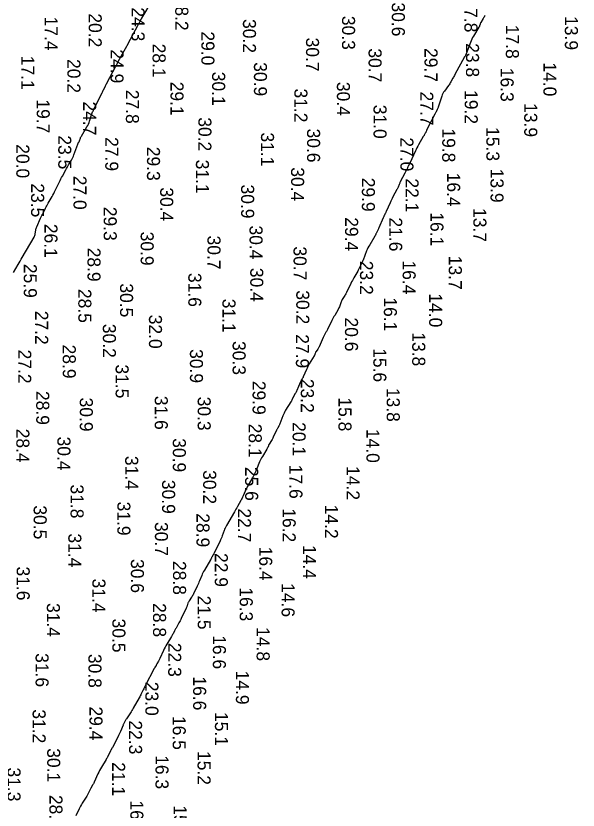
# Model space of a CAD drawing. Extents: x 1178573 to 1187098, y 693282 to 751751.
# Drawn here: x 1180061 to 1180599, y 711569 to 712330 of the extents above; entities that cross this region are included whole.
import ezdxf

# ---------------------------------------------------------------- set-up
doc = ezdxf.new("R2010")
doc.units = 0
doc.layers.add('V-HYDS-MAJR', color=7, linetype='Continuous')
doc.layers.add('V-HYDS-SOUN', color=7, linetype='Continuous')

msp = doc.modelspace()

# ---------------------------------------------------------------- linework, layer by layer
at = {"layer": 'V-HYDS-MAJR'}
for points in [[(1180058.4, 712084.02), (1180062.67, 712091.72), (1180063.61, 712093.4), (1180064.56, 712095.08), (1180065.52, 712096.75), (1180066.49, 712098.42), (1180078.04, 712118.1), (1180078.44, 712118.85), (1180078.75, 712119.63), (1180078.99, 712120.43), (1180079.14, 712121.27), (1180079.62, 712124.66), (1180079.77, 712125.5), (1180079.97, 712126.32), (1180080.23, 712127.12), (1180080.55, 712127.91), (1180084.2, 712136.14), (1180084.76, 712137.37), (1180085.33, 712138.59), (1180085.93, 712139.79), (1180086.55, 712140.99), (1180089.07, 712145.76), (1180089.7, 712146.95), (1180090.34, 712148.14), (1180090.99, 712149.32), (1180091.64, 712150.5), (1180095.2, 712156.86), (1180096.01, 712158.32), (1180096.79, 712159.79), (1180097.54, 712161.27), (1180098.27, 712162.77), (1180102.22, 712170.97), (1180102.92, 712172.39), (1180103.63, 712173.8), (1180104.36, 712175.2), (1180105.11, 712176.59), (1180108.36, 712182.51), (1180109.01, 712183.7), (1180109.68, 712184.89), (1180110.36, 712186.06), (1180111.05, 712187.23), (1180113.82, 712191.9), (1180114.49, 712193.09), (1180115.09, 712194.3), (1180115.64, 712195.53), (1180116.13, 712196.8), (1180119.84, 712207.19), (1180119.95, 712207.48), (1180120.08, 712207.75), (1180120.22, 712208.01), (1180120.38, 712208.27), (1180121.04, 712209.29), (1180121.19, 712209.55), (1180121.33, 712209.81), (1180121.46, 712210.09), (1180121.56, 712210.37), (1180122.42, 712212.89), (1180122.61, 712213.4), (1180122.83, 712213.9), (1180123.07, 712214.38), (1180123.34, 712214.85), (1180128.62, 712223.63), (1180129.38, 712224.97), (1180130.05, 712226.34), (1180130.65, 712227.74), (1180131.17, 712229.19), (1180133.46, 712236.16), (1180133.77, 712237.05), (1180134.11, 712237.93), (1180134.48, 712238.8), (1180134.87, 712239.65), (1180136.51, 712243.04), (1180136.92, 712243.89), (1180137.33, 712244.74), (1180137.75, 712245.58), (1180138.17, 712246.43), (1180143.06, 712256.23), (1180143.48, 712257.06), (1180143.89, 712257.89), (1180144.3, 712258.71), (1180144.72, 712259.54), (1180146.37, 712262.84), (1180146.79, 712263.67), (1180147.21, 712264.49), (1180147.64, 712265.31), (1180148.07, 712266.12), (1180156.09, 712281.13), (1180156.29, 712281.51), (1180156.48, 712281.89), (1180156.67, 712282.28), (1180156.86, 712282.66), (1180157.58, 712284.22), (1180157.77, 712284.6), (1180157.96, 712284.99), (1180158.16, 712285.37), (1180158.36, 712285.74), (1180167.17, 712301.63), (1180167.25, 712301.79), (1180167.34, 712301.94), (1180167.43, 712302.09), (1180167.52, 712302.24), (1180167.89, 712302.84), (1180167.98, 712302.99), (1180168.07, 712303.15), (1180168.16, 712303.3), (1180168.24, 712303.46), (1180177.45, 712320.96), (1180177.74, 712321.51), (1180178.03, 712322.06), (1180178.32, 712322.61), (1180178.61, 712323.16), (1180180.31, 712326.38), (1180180.32, 712326.41), (1180180.34, 712326.45), (1180180.35, 712326.48), (1180180.37, 712326.51), (1180180.43, 712326.64), (1180180.44, 712326.67), (1180180.46, 712326.7), (1180180.48, 712326.73), (1180180.49, 712326.76), (1180180.93, 712327.4), (1180181, 712327.52), (1180181.08, 712327.64), (1180181.15, 712327.76), (1180181.23, 712327.88), (1180191.16, 712344.58)], [(1180509.77, 712330.41), (1180509.42, 712329.63), (1180509.04, 712328.87), (1180508.64, 712328.11), (1180508.22, 712327.37), (1180506.02, 712323.66), (1180505.82, 712323.3), (1180505.64, 712322.93), (1180505.49, 712322.55), (1180505.35, 712322.15), (1180504.87, 712320.56), (1180504.74, 712320.17), (1180504.58, 712319.79), (1180504.4, 712319.42), (1180504.19, 712319.06), (1180499.06, 712310.73), (1180498.17, 712309.2), (1180497.36, 712307.64), (1180496.63, 712306.04), (1180495.97, 712304.4), (1180491.95, 712293.56), (1180491.9, 712293.44), (1180491.85, 712293.31), (1180491.8, 712293.19), (1180491.74, 712293.08), (1180491.51, 712292.61), (1180491.45, 712292.49), (1180491.39, 712292.37), (1180491.33, 712292.26), (1180491.27, 712292.14), (1180490.87, 712291.33), (1180490.78, 712291.16), (1180490.7, 712290.99), (1180490.61, 712290.82), (1180490.51, 712290.65), (1180481.22, 712273.84), (1180480.72, 712272.94), (1180480.22, 712272.04), (1180479.73, 712271.15), (1180479.23, 712270.25), (1180477.24, 712266.67), (1180476.73, 712265.79), (1180476.19, 712264.92), (1180475.63, 712264.07), (1180475.03, 712263.23), (1180471.19, 712257.99), (1180470.39, 712256.81), (1180469.7, 712255.58), (1180469.11, 712254.31), (1180468.61, 712252.98), (1180465.26, 712242.7), (1180465.05, 712242.11), (1180464.82, 712241.52), (1180464.56, 712240.94), (1180464.28, 712240.37), (1180463.11, 712238.12), (1180462.81, 712237.56), (1180462.52, 712237), (1180462.23, 712236.43), (1180461.94, 712235.87), (1180454.39, 712221.12), (1180454.24, 712220.83), (1180454.1, 712220.53), (1180453.97, 712220.23), (1180453.84, 712219.93), (1180453.34, 712218.72), (1180453.22, 712218.42), (1180453.08, 712218.13), (1180452.93, 712217.84), (1180452.77, 712217.55), (1180451.78, 712215.85), (1180451.56, 712215.47), (1180451.34, 712215.09), (1180451.12, 712214.71), (1180450.9, 712214.33), (1180446.37, 712206.47), (1180445.56, 712205.03), (1180444.78, 712203.57), (1180444.03, 712202.09), (1180443.32, 712200.59), (1180437.88, 712188.85), (1180437.7, 712188.46), (1180437.52, 712188.08), (1180437.33, 712187.7), (1180437.14, 712187.31), (1180436.38, 712185.79), (1180436.19, 712185.41), (1180436, 712185.03), (1180435.82, 712184.64), (1180435.64, 712184.26), (1180434.43, 712181.64), (1180434.16, 712181.08), (1180433.89, 712180.52), (1180433.61, 712179.96), (1180433.32, 712179.41), (1180428.87, 712170.94), (1180428.56, 712170.33), (1180428.27, 712169.72), (1180427.98, 712169.1), (1180427.71, 712168.48), (1180426.65, 712165.97), (1180426.38, 712165.35), (1180426.09, 712164.73), (1180425.8, 712164.12), (1180425.49, 712163.52), (1180421.85, 712156.55), (1180421.15, 712155.19), (1180420.46, 712153.81), (1180419.8, 712152.43), (1180419.16, 712151.03), (1180415.32, 712142.56), (1180415.09, 712142.05), (1180414.86, 712141.55), (1180414.62, 712141.04), (1180414.38, 712140.54), (1180413.41, 712138.52), (1180413.17, 712138.02), (1180412.94, 712137.51), (1180412.71, 712137), (1180412.49, 712136.49), (1180408.38, 712127.01), (1180408.12, 712126.42), (1180407.85, 712125.83), (1180407.57, 712125.25), (1180407.29, 712124.67), (1180405.77, 712121.66), (1180405.66, 712121.43), (1180405.55, 712121.2), (1180405.44, 712120.96), (1180405.34, 712120.73), (1180404.94, 712119.78), (1180404.83, 712119.55), (1180404.72, 712119.32), (1180404.6, 712119.09), (1180404.47, 712118.87), (1180399.5, 712110.73), (1180398.66, 712109.28), (1180397.88, 712107.8), (1180397.18, 712106.29), (1180396.54, 712104.75), (1180393.15, 712096.05), (1180393.02, 712095.72), (1180392.89, 712095.39), (1180392.74, 712095.06), (1180392.6, 712094.74), (1180392, 712093.44), (1180391.85, 712093.11), (1180391.7, 712092.79), (1180391.55, 712092.47), (1180391.39, 712092.15), (1180389.57, 712088.4), (1180389.2, 712087.67), (1180388.83, 712086.94), (1180388.45, 712086.22), (1180388.05, 712085.51), (1180384.39, 712079.03), (1180383.65, 712077.7), (1180382.94, 712076.37), (1180382.25, 712075.03), (1180381.57, 712073.67), (1180377.4, 712065.12), (1180377, 712064.33), (1180376.57, 712063.56), (1180376.12, 712062.79), (1180375.64, 712062.05), (1180373.68, 712059.09), (1180373.21, 712058.33), (1180372.79, 712057.56), (1180372.42, 712056.76), (1180372.1, 712055.93), (1180370.78, 712052.2), (1180370.44, 712051.31), (1180370.06, 712050.43), (1180369.64, 712049.57), (1180369.19, 712048.73), (1180365.98, 712043.07), (1180365.3, 712041.84), (1180364.63, 712040.61), (1180363.97, 712039.36), (1180363.33, 712038.12), (1180358.98, 712029.49), (1180358.66, 712028.85), (1180358.33, 712028.22), (1180358, 712027.59), (1180357.66, 712026.96), (1180356.3, 712024.44), (1180355.97, 712023.81), (1180355.65, 712023.18), (1180355.34, 712022.53), (1180355.04, 712021.89), (1180350.98, 712012.9), (1180350.72, 712012.36), (1180350.43, 712011.83), (1180350.12, 712011.32), (1180349.79, 712010.82), (1180348.13, 712008.47), (1180347.92, 712008.16), (1180347.75, 712007.84), (1180347.59, 712007.5), (1180347.47, 712007.15), (1180347.02, 712005.73), (1180346.89, 712005.38), (1180346.75, 712005.03), (1180346.59, 712004.7), (1180346.41, 712004.38), (1180341.67, 711996.49), (1180340.94, 711995.22), (1180340.25, 711993.93), (1180339.6, 711992.61), (1180338.99, 711991.27), (1180335.88, 711984.1), (1180335.67, 711983.65), (1180335.45, 711983.2), (1180335.22, 711982.75), (1180334.97, 711982.32), (1180333.95, 711980.59), (1180333.7, 711980.15), (1180333.46, 711979.71), (1180333.24, 711979.26), (1180333.04, 711978.8), (1180329.72, 711971.08), (1180329.39, 711970.35), (1180329.04, 711969.62), (1180328.67, 711968.91), (1180328.27, 711968.21), (1180326.26, 711964.77), (1180326.06, 711964.4), (1180325.86, 711964.02), (1180325.68, 711963.64), (1180325.5, 711963.25), (1180324.85, 711961.67), (1180324.67, 711961.28), (1180324.48, 711960.9), (1180324.28, 711960.52), (1180324.06, 711960.16), (1180318.97, 711952.16), (1180318.19, 711950.84), (1180317.47, 711949.49), (1180316.83, 711948.1), (1180316.25, 711946.68), (1180313.42, 711939.09), (1180313.22, 711938.57), (1180312.99, 711938.06), (1180312.75, 711937.56), (1180312.49, 711937.07), (1180311.41, 711935.12), (1180311.14, 711934.63), (1180310.88, 711934.14), (1180310.63, 711933.64), (1180310.39, 711933.13), (1180307.17, 711926.24), (1180306.8, 711925.48), (1180306.4, 711924.73), (1180305.98, 711923.99), (1180305.53, 711923.27), (1180303.26, 711919.7), (1180303.04, 711919.33), (1180302.83, 711918.94), (1180302.64, 711918.55), (1180302.46, 711918.15), (1180301.8, 711916.53), (1180301.62, 711916.12), (1180301.43, 711915.73), (1180301.23, 711915.34), (1180301.01, 711914.97), (1180296.74, 711907.97), (1180295.98, 711906.66), (1180295.28, 711905.33), (1180294.63, 711903.97), (1180294.05, 711902.58), (1180291.16, 711895.29), (1180290.88, 711894.6), (1180290.57, 711893.92), (1180290.25, 711893.25), (1180289.91, 711892.59), (1180288.52, 711889.95), (1180288.17, 711889.29), (1180287.82, 711888.64), (1180287.46, 711887.98), (1180287.09, 711887.33), (1180282.24, 711878.77), (1180281.67, 711877.72), (1180281.12, 711876.66), (1180280.61, 711875.58), (1180280.13, 711874.49), (1180278.26, 711870.08), (1180277.78, 711868.99), (1180277.27, 711867.91), (1180276.73, 711866.85), (1180276.15, 711865.8), (1180272.89, 711860.03), (1180272.15, 711858.72), (1180271.4, 711857.41), (1180270.66, 711856.11), (1180269.91, 711854.8), (1180262.31, 711841.62), (1180261.67, 711840.45), (1180261.08, 711839.25), (1180260.54, 711838.04), (1180260.05, 711836.8), (1180258.2, 711831.78), (1180257.72, 711830.54), (1180257.22, 711829.3), (1180256.69, 711828.08), (1180256.13, 711826.87), (1180250.53, 711815.15), (1180250.32, 711814.72), (1180250.1, 711814.3), (1180249.86, 711813.88), (1180249.61, 711813.48), (1180248.33, 711811.46), (1180248.21, 711811.25), (1180248.09, 711811.04), (1180247.99, 711810.82), (1180247.89, 711810.59), (1180247.54, 711809.68), (1180247.44, 711809.45), (1180247.34, 711809.23), (1180247.23, 711809.02), (1180247.11, 711808.8), (1180241.14, 711798.82), (1180240.44, 711797.61), (1180239.79, 711796.37), (1180239.18, 711795.11), (1180238.63, 711793.83), (1180236.48, 711788.65), (1180235.94, 711787.36), (1180235.38, 711786.07), (1180234.8, 711784.8), (1180234.21, 711783.53), (1180230.67, 711776.09), (1180230.26, 711775.28), (1180229.83, 711774.49), (1180229.37, 711773.71), (1180228.87, 711772.95), (1180226.52, 711769.46), (1180226.19, 711768.93), (1180225.9, 711768.39), (1180225.65, 711767.82), (1180225.44, 711767.24), (1180224.67, 711764.86), (1180224.46, 711764.27), (1180224.24, 711763.69), (1180224, 711763.12), (1180223.74, 711762.55), (1180219.03, 711752.69), (1180218.5, 711751.59), (1180217.95, 711750.51), (1180217.38, 711749.43), (1180216.79, 711748.36), (1180213.96, 711743.32), (1180213.59, 711742.65), (1180213.22, 711741.97), (1180212.87, 711741.3), (1180212.51, 711740.62), (1180211.11, 711737.88), (1180210.76, 711737.2), (1180210.39, 711736.53), (1180210.01, 711735.86), (1180209.61, 711735.2), (1180205.17, 711727.91), (1180204.32, 711726.47), (1180203.52, 711725.01), (1180202.76, 711723.53), (1180202.05, 711722.03), (1180198.42, 711714.13), (1180198.14, 711713.54), (1180197.85, 711712.95), (1180197.55, 711712.38), (1180197.24, 711711.8), (1180195.73, 711709.13), (1180195.52, 711708.76), (1180195.31, 711708.39), (1180195.1, 711708.03), (1180194.89, 711707.66), (1180194.02, 711706.21), (1180193.81, 711705.84), (1180193.6, 711705.47), (1180193.39, 711705.1), (1180193.19, 711704.73), (1180184.44, 711688.18), (1180183.94, 711687.24), (1180183.46, 711686.29), (1180182.99, 711685.33), (1180182.52, 711684.37), (1180180.69, 711680.52), (1180180.22, 711679.56), (1180179.74, 711678.6), (1180179.24, 711677.66), (1180178.73, 711676.73), (1180173.05, 711666.56), (1180172.4, 711665.42), (1180171.72, 711664.3), (1180171.03, 711663.19), (1180170.31, 711662.1), (1180166.6, 711656.55), (1180166.28, 711656.05), (1180165.97, 711655.55), (1180165.68, 711655.05), (1180165.39, 711654.54), (1180164.26, 711652.47), (1180163.99, 711651.95), (1180163.73, 711651.43), (1180163.48, 711650.9), (1180163.24, 711650.36), (1180160.63, 711644.18), (1180160.11, 711642.98), (1180159.56, 711641.79), (1180158.98, 711640.61), (1180158.39, 711639.44), (1180152.98, 711629.12), (1180152.79, 711628.76), (1180152.61, 711628.4), (1180152.42, 711628.04), (1180152.24, 711627.67), (1180151.5, 711626.22), (1180151.32, 711625.86), (1180151.14, 711625.5), (1180150.96, 711625.13), (1180150.78, 711624.77), (1180148.77, 711620.67), (1180148.37, 711619.88), (1180147.94, 711619.09), (1180147.5, 711618.31), (1180147.05, 711617.54), (1180142.49, 711610.1), (1180141.59, 711608.59), (1180140.75, 711607.06), (1180139.95, 711605.5), (1180139.2, 711603.91), (1180135.45, 711595.65), (1180135.11, 711594.93), (1180134.76, 711594.23), (1180134.4, 711593.53), (1180134.02, 711592.84), (1180132.38, 711589.95), (1180132.03, 711589.33), (1180131.69, 711588.71), (1180131.36, 711588.08), (1180131.04, 711587.45), (1180129.76, 711584.91), (1180129.43, 711584.28), (1180129.09, 711583.66), (1180128.74, 711583.05), (1180128.37, 711582.44), (1180124.08, 711575.52), (1180123.29, 711574.22), (1180122.55, 711572.89), (1180121.84, 711571.55), (1180121.16, 711570.19), (1180117.9, 711563.4)]]:
    msp.add_lwpolyline(points, dxfattribs=at)

# ---------------------------------------------------------------- texts
at = {"layer": 'V-HYDS-SOUN'}
for s, p in [('28.2 ', (1180213.27, 712348.42)), ('27.8 ', (1180490.29, 712346.75)), ('24.3 ', (1180171.39, 712338.19)), ('30.6 ', (1180420.73, 712342.88)), ('17.4 ', (1180088.09, 712329.4)), ('20.2 ', (1180130.3, 712332.44)), ('30.3 ', (1180373.03, 712330.05)), ('13.9 ', (1180586.52, 712329.79)), ('30.2 ', (1180278.1, 712326.99)), ('29.0 ', (1180238.25, 712315.13)), ('17.8 ', (1180529.99, 712321.49)), ('30.7 ', (1180338.51, 712309.21)), ('28.1 ', (1180191.54, 712303.43)), ('30.7 ', (1180398.45, 712298.91)), ('29.7 ', (1180452.03, 712299.21)), ('23.8 ', (1180491.8, 712303.84)), ('17.1 ', (1180065.69, 712291.82)), ('24.9 ', (1180151.22, 712297.93)), ('20.2 ', (1180109.9, 712288.67)), ('30.9 ', (1180288.62, 712285.63)), ('14.0 ', (1180565.97, 712285.44)), ('30.1 ', (1180248.57, 712276.5)), ('16.3 ', (1180524.96, 712280.28)), ('29.1 ', (1180208.67, 712266.98)), ('31.2 ', (1180327.38, 712260.46)), ('30.4 ', (1180368.11, 712266.8)), ('27.8 ', (1180165.98, 712259.21)), ('27.7 ', (1180447.99, 712257.54)), ('19.2 ', (1180490.57, 712258.92)), ('19.7 ', (1180080.48, 712250.03)), ('24.7 ', (1180125, 712248)), ('31.0 ', (1180403.21, 712244.86)), ('13.9 ', (1180547.58, 712246.42)), ('30.2 ', (1180235.39, 712232.87)), ('30.6 ', (1180339.53, 712222.08)), ('15.3 ', (1180511.28, 712223.46)), ('23.5 ', (1180101.16, 712215.56)), ('31.1 ', (1180295.38, 712218.33)), ('19.8 ', (1180469.04, 712222.18)), ('20.0 ', (1180060.96, 712207.03)), ('27.9 ', (1180146.2, 712213.84)), ('27.0 ', (1180428.93, 712213.62)), ('29.3 ', (1180186.15, 712204.59)), ('31.1 ', (1180233.05, 712192.25)), ('30.4 ', (1180324.24, 712184.95)), ('27.0 ', (1180115.71, 712176.84)), ('16.4 ', (1180473.72, 712179.76)), ('13.9 ', (1180515.29, 712183.59)), ('23.5 ', (1180075.14, 712169.56)), ('29.9 ', (1180392, 712174.96)), ('22.1 ', (1180433.9, 712174.3)), ('30.4 ', (1180198.82, 712165.69)), ('30.9 ', (1180276.35, 712168.44)), ('29.3 ', (1180144.68, 712147.08)), ('16.1 ', (1180457.75, 712141.82)), ('13.7 ', (1180498.85, 712145.9)), ('29.4 ', (1180375.95, 712137.08)), ('21.6 ', (1180418.24, 712136.87)), ('26.1 ', (1180087.9, 712130.76)), ('30.9 ', (1180180.09, 712123.29)), ('30.4 ', (1180284.41, 712129.17)), ('30.7 ', (1180244.12, 712119.52)), ('30.7 ', (1180326.57, 712109.12)), ('28.9 ', (1180129.17, 712107.94)), ('23.2 ', (1180390.24, 712095.33)), ('16.4 ', (1180431.1, 712095.64)), ('13.7 ', (1180475.32, 712100.16)), ('25.9 ', (1180068.12, 712092.42)), ('30.4 ', (1180285.1, 712088.59)), ('31.6 ', (1180225.75, 712083.69)), ('30.5 ', (1180160.34, 712073.73)), ('28.5 ', (1180120.38, 712068.38)), ('30.2 ', (1180329.19, 712067.09)), ('14.0 ', (1180456.46, 712064.12)), ('31.1 ', (1180258.47, 712059.01)), ('16.1 ', (1180413.1, 712060.29)), ('27.2 ', (1180079.02, 712047.5)), ('32.0 ', (1180188.05, 712043.67)), ('20.6 ', (1180375.85, 712041.01)), ('30.2 ', (1180143.88, 712034.93)), ('27.9 ', (1180328.81, 712024.96)), ('13.8 ', (1180440.29, 712026.83)), ('30.3 ', (1180268.21, 712018.47)), ('27.2 ', (1180062.81, 712010.26)), ('28.9 ', (1180105.45, 712015.06)), ('30.9 ', (1180227.3, 712010.72)), ('15.6 ', (1180403.01, 712011.61)), ('31.5 ', (1180156.11, 711996.04)), ('29.9 ', (1180287.31, 711980.35)), ('23.2 ', (1180333.55, 711982.24)), ('13.8 ', (1180415.85, 711973.59)), ('28.9 ', (1180080.06, 711970.63)), ('30.9 ', (1180121.79, 711964.27)), ('31.6 ', (1180193.6, 711965.97)), ('30.3 ', (1180234.71, 711965.15)), ('15.8 ', (1180369.63, 711964.46)), ('20.1 ', (1180325.67, 711940.74)), ('28.4 ', (1180060.99, 711934.46)), ('28.1 ', (1180283.6, 711939.29)), ('14.0 ', (1180396.39, 711934.29)), ('30.4 ', (1180100.36, 711926.91)), ('30.9 ', (1180210.9, 711925.33)), ('31.4 ', (1180165.29, 711908.41)), ('25.6 ', (1180280.21, 711897.87)), ('17.6 ', (1180322.6, 711899.9)), ('14.2 ', (1180377.35, 711898.62)), ('30.2 ', (1180239.98, 711894.74)), ('31.8 ', (1180112.97, 711881)), ('30.9 ', (1180200.63, 711885.46)), ('31.9 ', (1180157.78, 711864.6)), ('30.5 ', (1180077.57, 711861)), ('22.7 ', (1180273.32, 711858.07)), ('16.2 ', (1180316.13, 711858.23)), ('14.2 ', (1180356.68, 711861.64)), ('28.9 ', (1180233.57, 711853.41)), ('30.7 ', (1180193.76, 711845.04)), ('31.4 ', (1180110.79, 711834.1)), ('16.4 ', (1180293.7, 711821.37)), ('14.4 ', (1180335.69, 711823.01)), ('22.9 ', (1180251.09, 711815.35)), ('30.6 ', (1180170.73, 711809.58)), ('28.8 ', (1180211.13, 711807.74)), ('31.6 ', (1180061.32, 711802.43)), ('31.4 ', (1180133.86, 711790.89)), ('16.3 ', (1180275, 711782.48)), ('14.6 ', (1180315.12, 711786.48)), ('21.5 ', (1180234.75, 711774.52)), ('31.4 ', (1180090.22, 711767.4)), ('28.8 ', (1180191.94, 711767.32)), ('30.5 ', (1180152.99, 711752.54)), ('14.8 ', (1180291.21, 711744.32)), ('16.6 ', (1180249.27, 711736.58)), ('22.3 ', (1180206.49, 711729.26)), ('31.6 ', (1180079.43, 711719.39)), ('30.8 ', (1180130.06, 711718.67)), ('14.9 ', (1180271.36, 711702.65)), ('23.0 ', (1180184.61, 711691.94)), ('16.6 ', (1180230.38, 711697.08)), ('29.4 ', (1180131.07, 711668.28)), ('31.2 ', (1180076.59, 711665.55)), ('15.1 ', (1180251.26, 711663.01)), ('22.3 ', (1180168.96, 711654.95)), ('16.5 ', (1180210.8, 711659.23)), ('30.1 ', (1180090.56, 711628.3)), ('16.3 ', (1180194.32, 711621.62)), ('15.2 ', (1180234.6, 711625.62)), ('21.1 ', (1180152.73, 711614.92)), ('31.3 ', (1180052.52, 711609.84)), ('28.7 ', (1180092.71, 711583.56)), ('16.4 ', (1180170.21, 711578.22)), ('15.3 ', (1180211.77, 711573.65))]:
    msp.add_text(s, height=12.5, rotation=270, dxfattribs=at).set_placement(p)

doc.saveas('drawing.dxf')
